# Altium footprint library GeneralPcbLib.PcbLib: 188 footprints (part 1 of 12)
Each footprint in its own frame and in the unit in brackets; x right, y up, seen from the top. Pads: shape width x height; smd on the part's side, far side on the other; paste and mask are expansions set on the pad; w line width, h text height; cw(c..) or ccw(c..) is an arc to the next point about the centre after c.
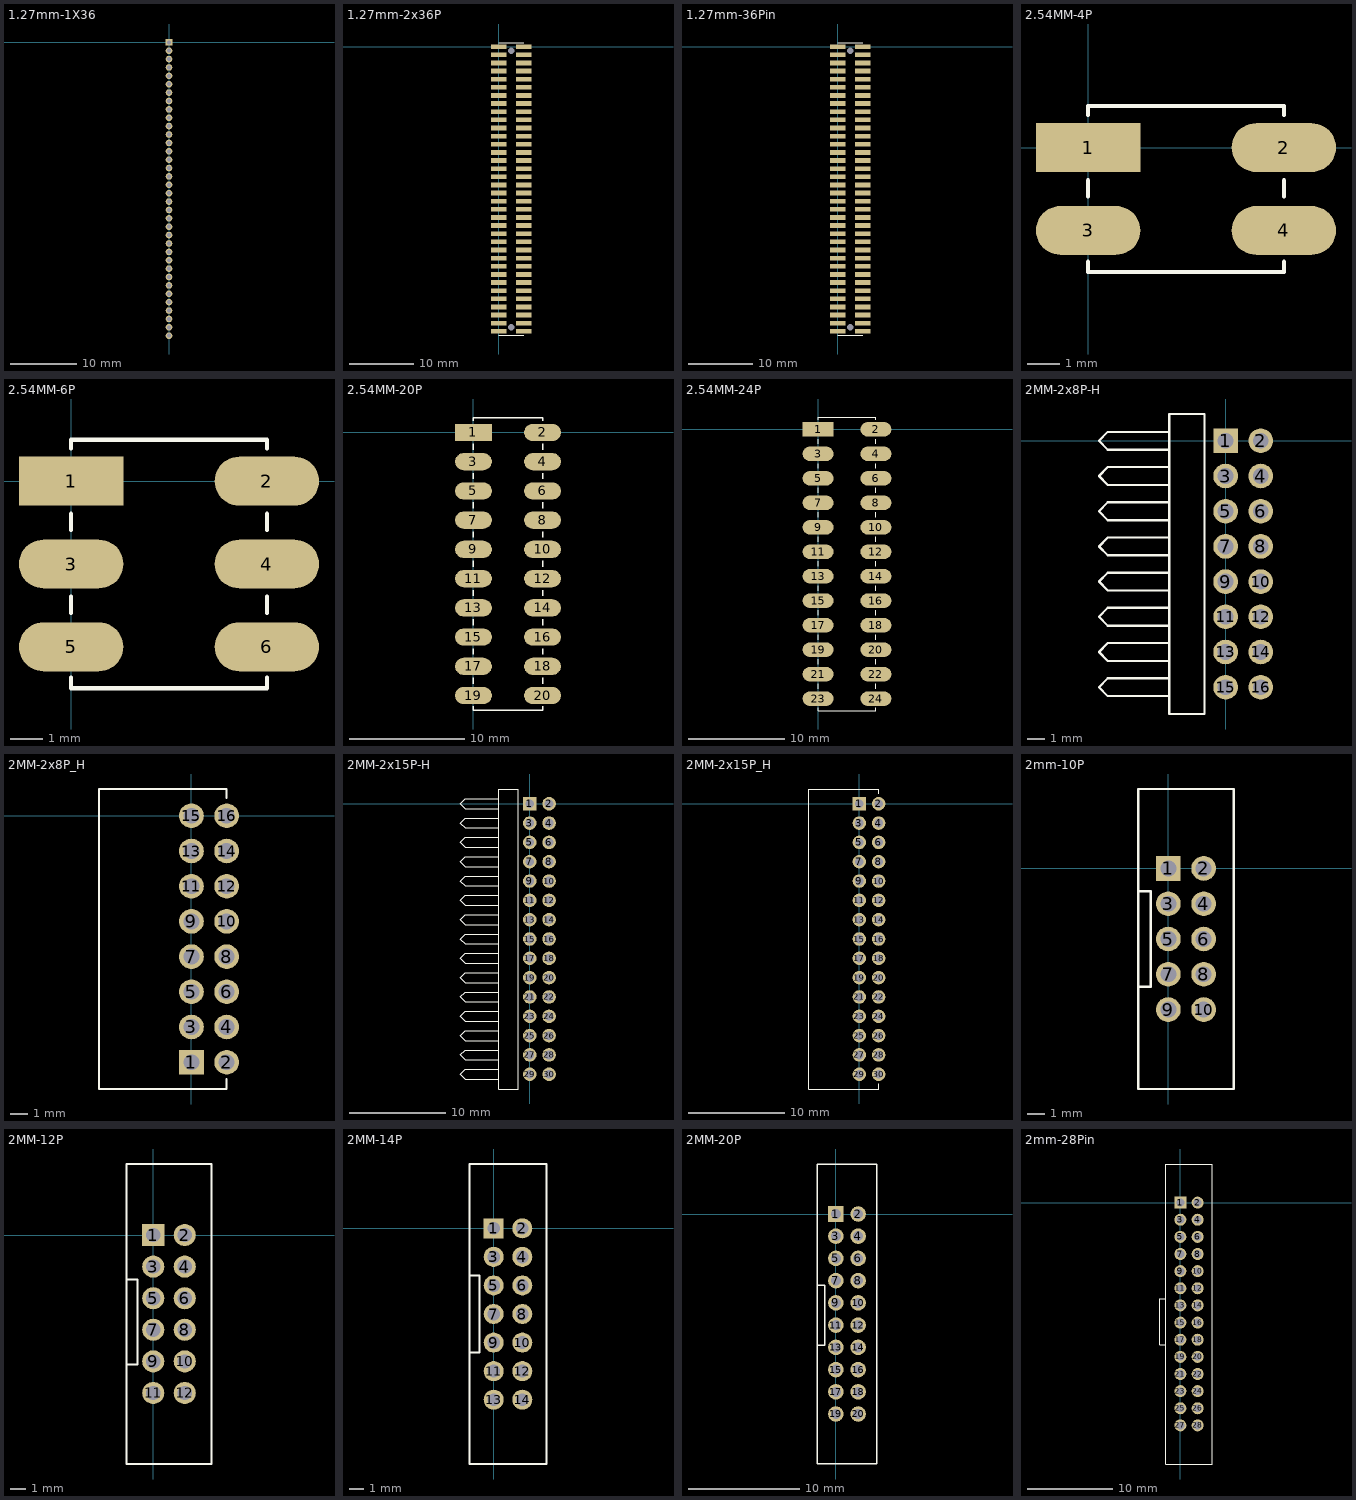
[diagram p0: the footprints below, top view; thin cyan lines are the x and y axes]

## 1.27mm-1X36 [mm]
pads (36):
  rect 1x1 hole 0.6: 1(0,0)
  round 1 hole 0.6: 2(0,-1.27) 3(0,-2.54) 4(0,-3.81) 5(0,-5.08) 6(0,-6.35) 7(0,-7.62) 8(0,-8.89) 9(0,-10.16) 10(0,-11.43) 11(0,-12.7) 12(0,-13.97) 13(0,-15.24) 14(0,-16.51) 15(0,-17.78) 16(0,-19.05) 17(0,-20.32) 18(0,-21.59) 19(0,-22.86) 20(0,-24.13) 21(0,-25.4) 22(0,-26.67) 23(0,-27.94) 24(0,-29.21) 25(0,-30.48) 26(0,-31.75) 27(0,-33.02) 28(0,-34.29) 29(0,-35.56) 30(0,-36.83) 31(0,-38.1) 32(0,-39.37) 33(0,-40.64) 34(0,-41.91) 35(0,-43.18) 36(0,-44.45)

## 1.27mm-2x36P [mm]
height 0.635
pads (75):
  round 0.7 hole 1.05: 0(1.95,-43.815) 0(1.95,-0.635)
  rect 2.4x0.74 smd: 1(0,0) 2(3.9,0) 3(0,-1.27) 4(3.9,-1.27) 5(0,-2.54) 6(3.9,-2.54) 7(0,-3.81) 8(3.9,-3.81) 9(0,-5.08) 10(3.9,-5.08) 11(0,-6.35) 12(3.9,-6.35) 13(0,-7.62) 14(3.9,-7.62) 15(0,-8.89) 16(3.9,-8.89) 17(0,-10.16) 18(3.9,-10.16) 19(0,-11.43) 20(3.9,-11.43) 21(0,-12.7) 22(3.9,-12.7) 23(0,-13.97) 24(3.9,-13.97) 25(0,-15.24) 26(3.9,-15.24) 27(0,-16.51) 28(3.9,-16.51) 29(0,-17.78) 30(3.9,-17.78) 31(0,-19.05) 32(3.9,-19.05) 33(0,-20.32) 34(3.9,-20.32) 35(0,-21.59) 36(3.9,-21.59) 37(0,-22.86) 38(3.9,-22.86) 39(0,-24.13) 40(3.9,-24.13) 41(0,-25.4) 42(3.9,-25.4) 43(0,-26.67) 44(3.9,-26.67) 45(0,-27.94) 46(3.9,-27.94) 47(0,-29.21) 48(3.9,-29.21) 49(0,-30.48) 50(3.9,-30.48) 51(0,-31.75) 52(3.9,-31.75) 53(0,-33.02) 54(3.9,-33.02) 55(0,-34.29) 56(3.9,-34.29) 57(0,-35.56) 58(3.9,-35.56) 59(0,-36.83) 60(3.9,-36.83) 61(0,-38.1) 62(3.9,-38.1) 63(0,-39.37) 64(3.9,-39.37) 65(0,-40.64) 66(3.9,-40.64) 67(0,-41.91) 68(3.9,-41.91) 69(0,-43.18) 70(3.9,-43.18) 71(0,-44.45) 72(3.9,-44.45)
  round 0.762 on Top Overlay: 2(-1.8,0)
Top Overlay:
  lines w0.127: 0,-45.085 3.9,-45.085 ; 0,0.635 3.9,0.635

## 1.27mm-36Pin [mm] "贴片"
pads (75):
  round 0.7 hole 1.05: 0(1.95,-43.815) 0(1.95,-0.635)
  rect 2.4x0.74 smd: 1(0,0) 2(3.9,0) 3(0,-1.27) 4(3.9,-1.27) 5(0,-2.54) 6(3.9,-2.54) 7(0,-3.81) 8(3.9,-3.81) 9(0,-5.08) 10(3.9,-5.08) 11(0,-6.35) 12(3.9,-6.35) 13(0,-7.62) 14(3.9,-7.62) 15(0,-8.89) 16(3.9,-8.89) 17(0,-10.16) 18(3.9,-10.16) 19(0,-11.43) 20(3.9,-11.43) 21(0,-12.7) 22(3.9,-12.7) 23(0,-13.97) 24(3.9,-13.97) 25(0,-15.24) 26(3.9,-15.24) 27(0,-16.51) 28(3.9,-16.51) 29(0,-17.78) 30(3.9,-17.78) 31(0,-19.05) 32(3.9,-19.05) 33(0,-20.32) 34(3.9,-20.32) 35(0,-21.59) 36(3.9,-21.59) 37(0,-22.86) 38(3.9,-22.86) 39(0,-24.13) 40(3.9,-24.13) 41(0,-25.4) 42(3.9,-25.4) 43(0,-26.67) 44(3.9,-26.67) 45(0,-27.94) 46(3.9,-27.94) 47(0,-29.21) 48(3.9,-29.21) 49(0,-30.48) 50(3.9,-30.48) 51(0,-31.75) 52(3.9,-31.75) 53(0,-33.02) 54(3.9,-33.02) 55(0,-34.29) 56(3.9,-34.29) 57(0,-35.56) 58(3.9,-35.56) 59(0,-36.83) 60(3.9,-36.83) 61(0,-38.1) 62(3.9,-38.1) 63(0,-39.37) 64(3.9,-39.37) 65(0,-40.64) 66(3.9,-40.64) 67(0,-41.91) 68(3.9,-41.91) 69(0,-43.18) 70(3.9,-43.18) 71(0,-44.45) 72(3.9,-44.45)
  round 0.762 on Top Overlay: 2(-1.8,0)
Top Overlay:
  lines w0.127: 0,-45.085 3.9,-45.085 ; 0,0.635 3.9,0.635

## 2.54MM-4P [mm] "贴片插针"
height 10
pads (4):
  rect 3.2x1.5 smd: 1(0,0)
  oval 3.2x1.5 smd: 2(6,0) 3(0,-2.54) 4(6,-2.54)
Top Overlay:
  lines w0.127: 0,-3.5 0,-3.81 6,-3.81 6,-3.5 ; 0,-1.5 0,-1 ; 0,1 0,1.27 6,1.27 6,1 ; 6,-1.5 6,-1

## 2.54MM-6P [mm]
pads (6):
  rect 3.2x1.5 smd: 1(0,0)
  oval 3.2x1.5 smd: 2(6,0) 3(0,-2.54) 4(6,-2.54) 5(0,-5.08) 6(6,-5.08)
Top Overlay:
  lines w0.127: 0,-6.02 0,-6.35 6,-6.35 6,-6.02 ; 0,-4.04 0,-3.54 ; 0,-1.5 0,-1 ; 0,1 0,1.27 6,1.27 6,1 ; 6,-4.04 6,-3.54 ; 6,-1.5 6,-1

## 2.54MM-20P [mm] "贴片插针"
height 10
pads (20):
  rect 3.2x1.5 smd: 1(0,0)
  oval 3.2x1.5 smd: 2(6,0) 3(0,-2.54) 4(6,-2.54) 5(0,-5.08) 6(6,-5.08) 7(0,-7.62) 8(6,-7.62) 9(0,-10.16) 10(6,-10.16) 11(0,-12.7) 12(6,-12.7) 13(0,-15.24) 14(6,-15.24) 15(0,-17.78) 16(6,-17.78) 17(0,-20.32) 18(6,-20.32) 19(0,-22.86) 20(6,-22.86)
Top Overlay:
  lines w0.127: 0,-23.8 0,-24.13 6,-24.13 6,-23.8 ; 0,-21.82 0,-21.32 ; 0,-19.28 0,-18.78 ; 0,-16.74 0,-16.24 ; 0,-14.2 0,-13.7 ; 0,-11.66 0,-11.16 ; 0,-9.12 0,-8.62 ; 0,-6.58 0,-6.08 ; 0,-4.04 0,-3.54 ; 0,-1.5 0,-1 ; 0,1 0,1.27 6,1.27 6,1 ; 6,-21.82 6,-21.32 ; 6,-19.28 6,-18.78 ; 6,-16.74 6,-16.24 ; 6,-14.2 6,-13.7 ; 6,-11.66 6,-11.16 ; 6,-9.12 6,-8.62 ; 6,-6.58 6,-6.08 ; 6,-4.04 6,-3.54 ; 6,-1.5 6,-1

## 2.54MM-24P [mm]
pads (24):
  rect 3.2x1.5 smd: 1(0,0)
  oval 3.2x1.5 smd: 2(6,0) 3(0,-2.54) 4(6,-2.54) 5(0,-5.08) 6(6,-5.08) 7(0,-7.62) 8(6,-7.62) 9(0,-10.16) 10(6,-10.16) 11(0,-12.7) 12(6,-12.7) 13(0,-15.24) 14(6,-15.24) 15(0,-17.78) 16(6,-17.78) 17(0,-20.32) 18(6,-20.32) 19(0,-22.86) 20(6,-22.86) 21(0,-25.4) 22(6,-25.4) 23(0,-27.94) 24(6,-27.94)
Top Overlay:
  lines w0.127: 0,-28.88 0,-29.21 6,-29.21 6,-28.88 ; 0,-26.9 0,-26.4 ; 0,-24.36 0,-23.86 ; 0,-21.82 0,-21.32 ; 0,-19.28 0,-18.78 ; 0,-16.74 0,-16.24 ; 0,-14.2 0,-13.7 ; 0,-11.66 0,-11.16 ; 0,-9.12 0,-8.62 ; 0,-6.58 0,-6.08 ; 0,-4.04 0,-3.54 ; 0,-1.5 0,-1 ; 0,1 0,1.27 6,1.27 6,1 ; 6,-26.9 6,-26.4 ; 6,-24.36 6,-23.86 ; 6,-21.82 6,-21.32 ; 6,-19.28 6,-18.78 ; 6,-16.74 6,-16.24 ; 6,-14.2 6,-13.7 ; 6,-11.66 6,-11.16 ; 6,-9.12 6,-8.62 ; 6,-6.58 6,-6.08 ; 6,-4.04 6,-3.54 ; 6,-1.5 6,-1

## 2MM-2x8P-H [mm] "侧向插针"
height 4
pads (16):
  rect 1.4x1.4 hole 0.9: 1(0,0)
  round 1.4 hole 0.9: 2(2,0) 3(0,-2) 4(2,-2) 5(0,-4) 6(2,-4) 7(0,-6) 8(2,-6) 9(0,-8) 10(2,-8) 11(0,-10) 12(2,-10) 13(0,-12) 14(2,-12) 15(0,-14) 16(2,-14)
Top Overlay:
  lines w0.127: -3.2,-14.508 -6.692,-14.508 -7.2,-14 -6.692,-13.492 -3.2,-13.492 ; -3.2,-12.508 -6.692,-12.508 -7.2,-12 -6.692,-11.492 -3.2,-11.492 ; -3.2,-10.508 -6.692,-10.508 -7.2,-10 -6.692,-9.492 -3.2,-9.492 ; -3.2,-8.508 -6.692,-8.508 -7.2,-8 -6.692,-7.492 -3.2,-7.492 ; -3.2,-6.508 -6.692,-6.508 -7.2,-6 -6.692,-5.492 -3.2,-5.492 ; -3.2,-4.508 -6.692,-4.508 -7.2,-4 -6.692,-3.492 -3.2,-3.492 ; -3.2,-2.508 -6.692,-2.508 -7.2,-2 -6.692,-1.492 -3.2,-1.492 ; -3.2,-0.508 -6.692,-0.508 -7.2,0 -6.692,0.508 -3.2,0.508 ; -3.2,-15.524 -3.2,1.524 -1.2,1.524 -1.2,-15.524 -3.2,-15.524

## 2MM-2x8P_H [mm] "侧向排母"
height 4
pads (16):
  rect 1.4x1.4 hole 0.9: 1(0,-14)
  round 1.4 hole 0.9: 2(2,-14) 3(0,-12) 4(2,-12) 5(0,-10) 6(2,-10) 7(0,-8) 8(2,-8) 9(0,-6) 10(2,-6) 11(0,-4) 12(2,-4) 13(0,-2) 14(2,-2) 15(0,0) 16(2,0)
Top Overlay:
  lines w0.127: 2,-14.956 2,-15.524 -5.25,-15.524 -5.25,1.524 2,1.524 2,1.016

## 2MM-2x15P-H [mm] "侧向排针"
height 4
pads (30):
  rect 1.4x1.4 hole 0.9: 1(0,0)
  round 1.4 hole 0.9: 2(2,0) 3(0,-2) 4(2,-2) 5(0,-4) 6(2,-4) 7(0,-6) 8(2,-6) 9(0,-8) 10(2,-8) 11(0,-10) 12(2,-10) 13(0,-12) 14(2,-12) 15(0,-14) 16(2,-14) 17(0,-16) 18(2,-16) 19(0,-18) 20(2,-18) 21(0,-20) 22(2,-20) 23(0,-22) 24(2,-22) 25(0,-24) 26(2,-24) 27(0,-26) 28(2,-26) 29(0,-28) 30(2,-28)
Top Overlay:
  lines w0.127: -3.2,-28.508 -6.692,-28.508 -7.2,-28 -6.692,-27.492 -3.2,-27.492 ; -3.2,-26.508 -6.692,-26.508 -7.2,-26 -6.692,-25.492 -3.2,-25.492 ; -3.2,-24.508 -6.692,-24.508 -7.2,-24 -6.692,-23.492 -3.2,-23.492 ; -3.2,-22.508 -6.692,-22.508 -7.2,-22 -6.692,-21.492 -3.2,-21.492 ; -3.2,-20.508 -6.692,-20.508 -7.2,-20 -6.692,-19.492 -3.2,-19.492 ; -3.2,-18.508 -6.692,-18.508 -7.2,-18 -6.692,-17.492 -3.2,-17.492 ; -3.2,-16.508 -6.692,-16.508 -7.2,-16 -6.692,-15.492 -3.2,-15.492 ; -3.2,-14.508 -6.692,-14.508 -7.2,-14 -6.692,-13.492 -3.2,-13.492 ; -3.2,-12.508 -6.692,-12.508 -7.2,-12 -6.692,-11.492 -3.2,-11.492 ; -3.2,-10.508 -6.692,-10.508 -7.2,-10 -6.692,-9.492 -3.2,-9.492 ; -3.2,-8.508 -6.692,-8.508 -7.2,-8 -6.692,-7.492 -3.2,-7.492 ; -3.2,-6.508 -6.692,-6.508 -7.2,-6 -6.692,-5.492 -3.2,-5.492 ; -3.2,-4.508 -6.692,-4.508 -7.2,-4 -6.692,-3.492 -3.2,-3.492 ; -3.2,-2.508 -6.692,-2.508 -7.2,-2 -6.692,-1.492 -3.2,-1.492 ; -3.2,-0.508 -6.692,-0.508 -7.2,0 -6.692,0.508 -3.2,0.508 ; -3.2,-29.524 -3.2,1.524 -1.2,1.524 -1.2,-29.524 -3.2,-29.524

## 2MM-2x15P_H [mm] "侧向排母"
height 4
pads (30):
  rect 1.4x1.4 hole 0.9: 1(0,0)
  round 1.4 hole 0.9: 2(2,0) 3(0,-2) 4(2,-2) 5(0,-4) 6(2,-4) 7(0,-6) 8(2,-6) 9(0,-8) 10(2,-8) 11(0,-10) 12(2,-10) 13(0,-12) 14(2,-12) 15(0,-14) 16(2,-14) 17(0,-16) 18(2,-16) 19(0,-18) 20(2,-18) 21(0,-20) 22(2,-20) 23(0,-22) 24(2,-22) 25(0,-24) 26(2,-24) 27(0,-26) 28(2,-26) 29(0,-28) 30(2,-28)
Top Overlay:
  lines w0.127: 2,-28.956 2,-29.524 -5.25,-29.524 -5.25,1.524 2,1.524 2,1.016

## 2mm-10P [mm] "10P线插座"
pads (10):
  rect 1.4x1.4 hole 0.9: 1(0,0)
  round 1.4 hole 0.9: 2(2,0) 3(0,-2) 4(2,-2) 5(0,-4) 6(2,-4) 7(0,-6) 8(2,-6) 9(0,-8) 10(2,-8)
Top Overlay:
  lines w0.127: -1.7,-6.7 -1.1,-6.7 -1,-6.7 -1,-1.3 -1.7,-1.3 ; -1.7,-12.5 3.7,-12.5 3.7,4.5 -1.7,4.5 -1.7,-12.5

## 2MM-12P [mm]
pads (12):
  rect 1.4x1.4 hole 0.9: 1(0,0)
  round 1.4 hole 0.9: 2(2,0) 3(0,-2) 4(2,-2) 5(0,-4) 6(2,-4) 7(0,-6) 8(2,-6) 9(0,-8) 10(2,-8) 11(0,-10) 12(2,-10)
Top Overlay:
  lines w0.127: -1.7,-8.2 -1.1,-8.2 -1,-8.2 -1,-2.8 -1.7,-2.8 ; -1.7,-14.5 -1.7,4.5 3.7,4.5 3.7,-14.5 -1.7,-14.5

## 2MM-14P [mm]
pads (14):
  rect 1.4x1.4 hole 0.9: 1(0,0)
  round 1.4 hole 0.9: 2(2,0) 3(0,-2) 4(2,-2) 5(0,-4) 6(2,-4) 7(0,-6) 8(2,-6) 9(0,-8) 10(2,-8) 11(0,-10) 12(2,-10) 13(0,-12) 14(2,-12)
Top Overlay:
  lines w0.127: -1.7,-8.7 -1.1,-8.7 -1,-8.7 -1,-3.3 -1.7,-3.3 ; -1.7,-16.5 3.7,-16.5 3.7,4.5 -1.7,4.5 -1.7,-16.5

## 2MM-20P [mm]
pads (20):
  rect 1.4x1.4 hole 0.9: 1(0,0)
  round 1.4 hole 0.9: 2(2,0) 3(0,-2) 4(2,-2) 5(0,-4) 6(2,-4) 7(0,-6) 8(2,-6) 9(0,-8) 10(2,-8) 11(0,-10) 12(2,-10) 13(0,-12) 14(2,-12) 15(0,-14) 16(2,-14) 17(0,-16) 18(2,-16) 19(0,-18) 20(2,-18)
Top Overlay:
  lines w0.127: -1.7,-11.8 -1.1,-11.8 -1,-11.8 -1,-6.4 -1.7,-6.4 ; -1.7,-22.5 -1.7,4.5 3.7,4.5 3.7,-22.5 -1.7,-22.5

## 2mm-28Pin [mm]
pads (28):
  rect 1.4x1.4 hole 0.9: 1(0,0)
  round 1.4 hole 0.9: 2(2,0) 3(0,-2) 4(2,-2) 5(0,-4) 6(2,-4) 7(0,-6) 8(2,-6) 9(0,-8) 10(2,-8) 11(0,-10) 12(2,-10) 13(0,-12) 14(2,-12) 15(0,-14) 16(2,-14) 17(0,-16) 18(2,-16) 19(0,-18) 20(2,-18) 21(0,-20) 22(2,-20) 23(0,-22) 24(2,-22) 25(0,-24) 26(2,-24) 27(0,-26) 28(2,-26)
Top Overlay:
  lines w0.127: -1.7,-16.6 -2.3,-16.6 -2.4,-16.6 -2.4,-11.2 -1.7,-11.2 ; -1.7,-30.5 3.7,-30.5 3.7,4.5 -1.7,4.5 -1.7,-30.5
